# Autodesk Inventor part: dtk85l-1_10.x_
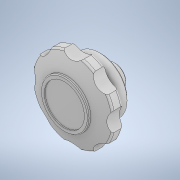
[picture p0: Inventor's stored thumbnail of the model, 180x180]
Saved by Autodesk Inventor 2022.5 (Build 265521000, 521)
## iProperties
Created: 2023-06
Part Number: dtk85l-1_10.x_
Material: Generic
Document SubType Name: Modeling
Designer: ImaoCorp
Density: 1 g/cm^3
Appearance: Default
Sending System: SOLIDWORKS 2021-2021301
MC: AMD64
MC_MODEL: Intel64 Family 6 Model 60 Stepping 3, GenuineIntel
OS: Windows_NT
FRU: Parasolid Version 32.1, build 255,  1- 1-2021
FORMAT: text
GUISE: transmit
KEY: dtk85l-1_10
FILE: dtk85l-1_10.x_t
DATE: Thu Jun 15 15:47:46 2023
Author: ImaoCorp
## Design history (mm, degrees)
feature "Base1"
node "ソリッド1"
